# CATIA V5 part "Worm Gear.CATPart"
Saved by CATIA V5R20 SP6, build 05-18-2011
Part number: Worm Gear
Bounding box of the stored display mesh (mm): x -11.5 to 11.5, y -11.5 to 11.5, z -26.329 to 18.671
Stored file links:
  E:\#01 CATIA Lecture Materials\#06 DMU\#06 DMU Page01 KIN EX06\Worm Gear.CATPart
  C:\usr\cao_3d\cad\catiaV5\cours\gt\gear\bevel_gear\8_bevel_gear.CATPart
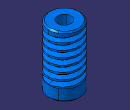
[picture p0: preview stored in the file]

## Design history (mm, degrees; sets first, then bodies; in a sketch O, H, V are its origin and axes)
Body1 (main body)
  Solid1: solid without history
